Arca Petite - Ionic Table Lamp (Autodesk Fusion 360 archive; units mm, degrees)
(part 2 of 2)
design "Balon v2"
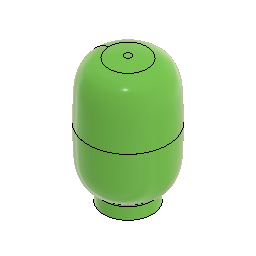
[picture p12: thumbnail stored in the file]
derived_base_feature "Derived Base Feature" bodies "Balon"
work_plane "WorkPlane1" AlongDistance 0
sketch "Sketch1" plane through (0, 0, 0) normal (0, 1, 0) x axis (1, 0, 0)
  line L1 (0, 317.5) -> (0, 2.9083)
  curve K1 (-82.9821, 124.2212) -> (-50.8, 237.8015)
  curve K2 (-51.0925, 237.681) -> (-50.8, 237.8015)
  curve K3 (-51.3855, 237.5558) -> (-51.0925, 237.681)
  curve K4 (-54.7608, 236.0513) -> (-51.3855, 237.5558)
  curve K5 (-57.9615, 234.05) -> (-54.7608, 236.0513)
  curve K6 (-67.2727, 226.749) -> (-57.9615, 234.05)
  curve K7 (-69.0552, 224.2615) -> (-67.2727, 226.749)
  curve K8 (-72.1872, 218.7832) -> (-69.0552, 224.2615)
  curve K9 (-74.1213, 215.1556) -> (-72.1872, 218.7832)
  curve K10 (-78.3031, 204.3965) -> (-74.1213, 215.1556)
  curve K11 (-79.7275, 197.3397) -> (-78.3031, 204.3965)
  curve K12 (-81.3333, 185.4664) -> (-79.7275, 197.3397)
  curve K13 (-81.6254, 178.4008) -> (-81.3333, 185.4664)
  curve K14 (-82.49, 152.2133) -> (-81.6254, 178.4008)
  curve K15 (-82.9821, 136.067) -> (-82.49, 152.2133)
  curve K16 (-82.9821, 124.2212) -> (-82.9821, 136.067)
  curve K17 (50.8, 237.7999) -> (82.9821, 124.2212)
  curve K18 (82.9821, 140.3031) -> (82.9821, 124.2212)
  curve K19 (81.9353, 169.4257) -> (82.9821, 140.3031)
  curve K20 (81.3621, 183.6489) -> (81.9353, 169.4257)
  curve K21 (80.9478, 189.8724) -> (81.3621, 183.6489)
  curve K22 (77.8147, 206.9858) -> (80.9478, 189.8724)
  curve K23 (74.9652, 213.2153) -> (77.8147, 206.9858)
  curve K24 (69.4688, 224.1531) -> (74.9652, 213.2153)
  curve K25 (67.2512, 226.458) -> (69.4688, 224.1531)
  curve K26 (61.5696, 231.3138) -> (67.2512, 226.458)
  curve K27 (57.377, 234.6711) -> (61.5696, 231.3138)
  curve K28 (52.0556, 237.2628) -> (57.377, 234.6711)
  curve K29 (51.4313, 237.5413) -> (52.0556, 237.2628)
  curve K30 (50.8, 237.7999) -> (51.4313, 237.5413)
  line L2 (-50.8, 317.5) -> (-50.8, 237.8015)
  line L3 (50.8, 317.5) -> (50.8, 237.7999)
  line L4 (-19.0713, 6.7501) -> (-19.0713, 6.7501)
  curve K31 (82.9821, 124.1958) -> (40.1509, 7.3012)
  curve K32 (41.8198, 7.6176) -> (40.1509, 7.3012)
  curve K33 (43.2113, 8.0663) -> (41.8198, 7.6176)
  curve K34 (47.0139, 9.2854) -> (43.2113, 8.0663)
  curve K35 (47.3314, 9.3805) -> (47.0139, 9.2854)
  curve K36 (50.1192, 10.3272) -> (47.3314, 9.3805)
  curve K37 (51.833, 11.0085) -> (50.1192, 10.3272)
  curve K38 (57.8313, 14.1895) -> (51.833, 11.0085)
  curve K39 (61.4491, 17.0488) -> (57.8313, 14.1895)
  curve K40 (66.8203, 21.5867) -> (61.4491, 17.0488)
  curve K41 (68.5372, 23.5528) -> (66.8203, 21.5867)
  curve K42 (71.2201, 27.8971) -> (68.5372, 23.5528)
  curve K43 (74.7424, 33.8984) -> (71.2201, 27.8971)
  curve K44 (78.2342, 44.8406) -> (74.7424, 33.8984)
  curve K45 (79.6792, 50.3463) -> (78.2342, 44.8406)
  curve K46 (81.3558, 63.5576) -> (79.6792, 50.3463)
  curve K47 (81.6386, 70.4415) -> (81.3558, 63.5576)
  curve K48 (82.4897, 96.2198) -> (81.6386, 70.4415)
  curve K49 (82.9814, 112.3523) -> (82.4897, 96.2198)
  curve K50 (82.9821, 124.1958) -> (82.9814, 112.3523)
  curve K51 (-40.1501, 7.301) -> (-82.9821, 124.1958)
  curve K52 (-82.9813, 110.5256) -> (-82.9821, 124.1958)
  curve K53 (-82.2545, 88.8594) -> (-82.9813, 110.5256)
  curve K54 (-81.6277, 70.519) -> (-82.2545, 88.8594)
  curve K55 (-81.3572, 64.3441) -> (-81.6277, 70.519)
  curve K56 (-79.4149, 46.8924) -> (-81.3572, 64.3441)
  curve K57 (-76.5204, 38.9768) -> (-79.4149, 46.8924)
  curve K58 (-73.5142, 32.2947) -> (-76.5204, 38.9768)
  curve K59 (-72.5556, 30.3818) -> (-73.5142, 32.2947)
  curve K60 (-69.7914, 25.3691) -> (-72.5556, 30.3818)
  curve K61 (-68.3824, 23.4028) -> (-69.7914, 25.3691)
  curve K62 (-64.5419, 19.5456) -> (-68.3824, 23.4028)
  curve K63 (-62.3002, 17.7646) -> (-64.5419, 19.5456)
  curve K64 (-53.6583, 11.1976) -> (-62.3002, 17.7646)
  curve K65 (-49.6968, 10.1396) -> (-53.6583, 11.1976)
  curve K66 (-43.4141, 8.1331) -> (-49.6968, 10.1396)
  curve K67 (-41.9704, 7.6516) -> (-43.4141, 8.1331)
  curve K68 (-40.1963, 7.3098) -> (-41.9704, 7.6516)
  curve K69 (-40.1732, 7.3054) -> (-40.1963, 7.3098)
  curve K70 (-40.1501, 7.301) -> (-40.1732, 7.3054)
  line L5 (-82.9821, 124.1958) -> (-82.9821, 124.2212)
  line L6 (82.9821, 124.2212) -> (82.9821, 124.1958)
  line L7 (0, 317.5) -> (-50.8, 317.5)
  line L8 (7.2015, 3.048) -> (0, 3.048)
  line L9 (0, 3.048) -> (-7.2015, 3.048)
  arc A1 centre (0, 188.595) radius 185.6867 clockwise from (-7.2015, 3.048) to (-40.1502, 7.301)
  arc A2 centre (0, 188.595) radius 185.6867 clockwise from (40.151, 7.3012) to (7.2015, 3.048)
  point P38 (-40.1502, 7.301)
  point P43 (40.1509, 7.3012)
  point P62 (-40.1501, 7.301)
  point P81 (40.151, 7.3012)
  point P84 (0, 3.048)
  vertical L1
  horizontal L4
  coincident P38 K51
  symmetric L1 A1 A2
  coincident A2 P43
  coincident A1 P62
  coincident K31 P81
  perpendicular L2 L7
  horizontal L8
  coincident L1 P84
  horizontal L9
revolve "Revolve1" sketch "Sketch1" AlongAngle 360
shell "Shell1" innerThickness 3.81
fillet "Fillet1" radius 6.35
offset_faces "OffsetFaces1" distance -50.8
move "Move1"
move "Move2"
component_from_bodies "Body->Comp1"
component_from_bodies "Body->Comp2"
sketch "Sketch2" plane through (0, 0, 0) normal (0, 1, 0) x axis (1, 0, 0)
  line L1 (-85.5221, 124.2212) -> (-85.5221, 124.1961)
  curve K1 (-58.9057, 236.4383) -> (-50.8, 241.7989)
  curve K2 (-50.8, 241.554) -> (-50.8, 241.7989)
  curve K3 (-50.904, 240.933) -> (-50.8, 241.554)
  curve K4 (-51.2936, 240.2837) -> (-50.904, 240.933)
  curve K5 (-51.734, 239.7561) -> (-51.2936, 240.2837)
  curve K6 (-53.328, 238.5038) -> (-51.734, 239.7561)
  curve K7 (-54.0892, 238.1997) -> (-53.328, 238.5038)
  curve K8 (-58.9057, 236.4383) -> (-54.0892, 238.1997)
  curve K9 (-89.3309, 124.2212) -> (-58.9057, 236.4383)
  curve K10 (-62.6336, 234.9735) -> (-58.9057, 236.4383)
  curve K11 (-65.581, 233.1032) -> (-62.6336, 234.9735)
  curve K12 (-73.0224, 227.0019) -> (-65.581, 233.1032)
  curve K13 (-74.8981, 224.836) -> (-73.0224, 227.0019)
  curve K14 (-78.1104, 219.6097) -> (-74.8981, 224.836)
  curve K15 (-80.2663, 215.561) -> (-78.1104, 219.6097)
  curve K16 (-84.0943, 205.8277) -> (-80.2663, 215.561)
  curve K17 (-85.4655, 200.1154) -> (-84.0943, 205.8277)
  curve K18 (-87.4092, 188.5789) -> (-85.4655, 200.1154)
  curve K19 (-87.7349, 182.3889) -> (-87.4092, 188.5789)
  curve K20 (-88.4233, 165.9645) -> (-87.7349, 182.3889)
  curve K21 (-89.328, 138.6964) -> (-88.4233, 165.9645)
  curve K22 (-89.3309, 124.2212) -> (-89.328, 138.6964)
  line L2 (-89.3309, 124.1958) -> (-89.3309, 124.2212)
  curve K23 (-46.5001, 7.301) -> (-89.3309, 124.1958)
  curve K24 (-89.3314, 112.4293) -> (-89.3309, 124.1958)
  curve K25 (-88.8181, 95.3068) -> (-89.3314, 112.4293)
  curve K26 (-88.346, 81.2892) -> (-88.8181, 95.3068)
  curve K27 (-88.0298, 70.4902) -> (-88.346, 81.2892)
  curve K28 (-87.1514, 58.328) -> (-88.0298, 70.4902)
  curve K29 (-86.3326, 50.6119) -> (-87.1514, 58.328)
  curve K30 (-81.0932, 33.6688) -> (-86.3326, 50.6119)
  curve K31 (-77.3163, 27.4309) -> (-81.0932, 33.6688)
  curve K32 (-74.8955, 23.6666) -> (-77.3163, 27.4309)
  curve K33 (-73.5108, 22.0741) -> (-74.8955, 23.6666)
  curve K34 (-70.2346, 19.0457) -> (-73.5108, 22.0741)
  curve K35 (-64.8094, 14.3548) -> (-70.2346, 19.0457)
  curve K36 (-56.6696, 10.3041) -> (-64.8094, 14.3548)
  curve K37 (-54.0053, 9.483) -> (-56.6696, 10.3041)
  curve K38 (-49.1487, 7.9411) -> (-54.0053, 9.483)
  curve K39 (-48.3482, 7.6526) -> (-49.1487, 7.9411)
  curve K40 (-46.5001, 7.301) -> (-48.3482, 7.6526)
  line L3 (0, 266.7) -> (0, 0)
  line L4 (0, 3.048) -> (-7.7894, 3.048)
  line L5 (-50.8, 266.7) -> (-50.8, 241.7989)
  line L6 (0, 266.7) -> (-50.8, 266.7)
  arc A1 centre (-6.9779, 188.7329) radius 185.6867 clockwise from (-7.7894, 3.048) to (-46.5001, 7.301)
  point P1 (0, 0)
  point P44 (0, 0)
  point P46 (0, 3.048)
  point P5 (-50.8, 241.554)
  point P49 (0, 266.7)
  coincident P1 P44
  coincident L3 P46
  coincident P5 L5
  coincident L3 P49
revolve "Revolve2" sketch "Sketch2" AlongAngle 360 bodies "Balon v3"
shell "Shell2" innerThickness 3.81
component_from_bodies "Body->Comp3"
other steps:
base_feature "Base Feature1" bodies "Balon"
base_feature "Base Feature1" bodies "Balon v3"
base_feature "Base Feature1" bodies "Balon v2"
create_component "CreateComponent1"
remove_body "RemoveBody1"
create_component "CreateComponent2"
remove_body "RemoveBody2"
create_component "CreateComponent3"
remove_body "RemoveBody3"
named bodies: "Balon", "Balon v2", "Balon v3"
